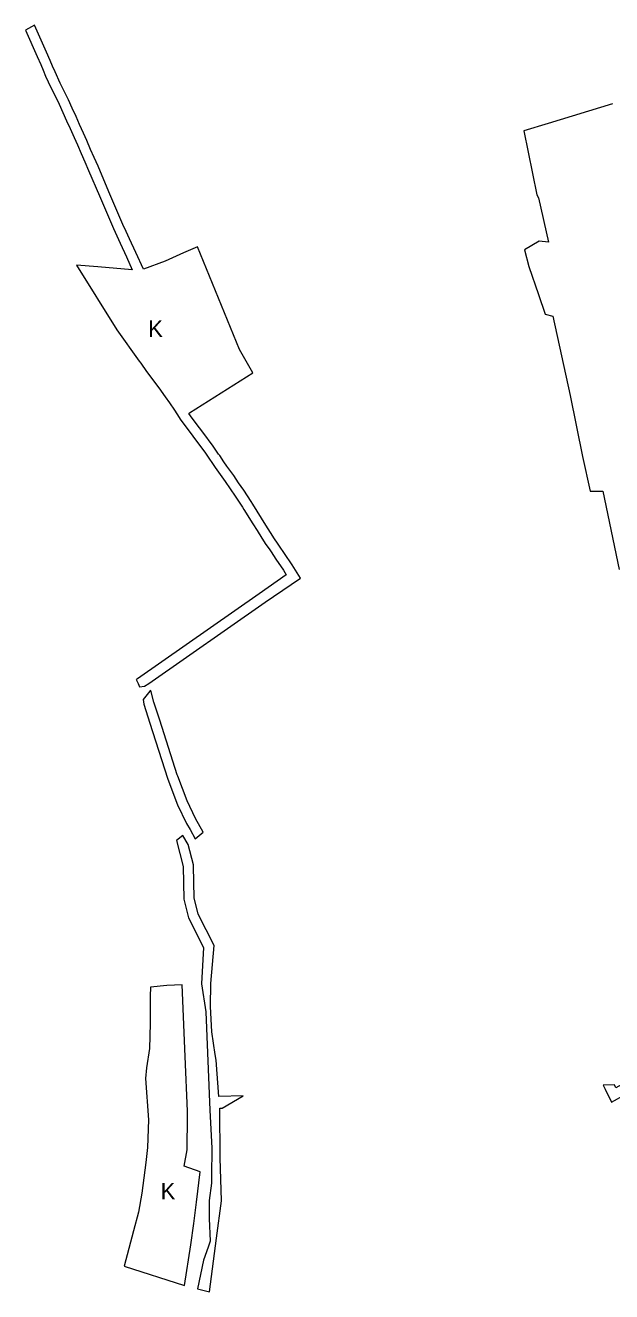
# Model space of a CAD drawing. Extents: x -650276 to -642489, y -1074425 to -1066658.
# Drawn here: x -649558 to -648708, y -1068954 to -1067116 of the extents above; entities that cross this region are included whole.
import ezdxf

# ---------------------------------------------------------------- set-up
doc = ezdxf.new("R2010")
doc.units = 0
doc.header["$LTSCALE"] = 9.6
for name, color, linetype, lineweight in [('1', 7, 'Continuous', 13), ('43', 7, 'Continuous', 13), ('47', 7, 'Continuous', 13)]:
    doc.layers.add(name, color=color, linetype=linetype, lineweight=lineweight)

msp = doc.modelspace()

# ---------------------------------------------------------------- linework, layer by layer
at = {"layer": '1'}
msp.add_lwpolyline([(-648706.47, -1067229.51), (-648800.02, -1067258.42), (-648835.29, -1067268.93), (-648816.06, -1067361.71), (-648813.81, -1067365.91), (-648799.58, -1067430.4), (-648812.91, -1067429.16), (-648834.01, -1067441.81), (-648827.86, -1067465.86), (-648813.94, -1067506.27), (-648804.08, -1067534.88), (-648792.97, -1067537.86), (-648767.84, -1067652.98), (-648749.97, -1067741.49), (-648738.7, -1067792.04), (-648720.34, -1067792), (-648696.93, -1067905.76)], dxfattribs=at)
at = {"layer": '47'}
for points in [[(-649545.203, -1067115.647), (-649549.7, -1067118.05), (-649558.469, -1067122.73), (-649541.537, -1067160.722), (-649536.075, -1067172.622), (-649532.831, -1067180.855), (-649529.013, -1067189.389), (-649521.663, -1067206.124), (-649514.869, -1067218.957), (-649509.44, -1067230.141), (-649504.224, -1067242.225), (-649498.572, -1067254.427), (-649493.526, -1067265.611), (-649487.812, -1067278.312), (-649482.963, -1067288.934), (-649477.677, -1067301.655), (-649472.327, -1067313.644), (-649466.703, -1067326.24), (-649451.059, -1067363.074), (-649439.265, -1067390.397), (-649430.531, -1067410.689), (-649425.804, -1067421.21), (-649421.071, -1067431.944), (-649411.913, -1067451.746), (-649403.34, -1067470.579)], [(-649387.17, -1067469.894), (-649398.28, -1067445.49), (-649407.4, -1067425.77), (-649412.1, -1067415.11), (-649416.8, -1067404.65), (-649425.49, -1067384.46), (-649437.27, -1067357.17), (-649452.95, -1067320.25), (-649458.63, -1067307.53), (-649463.9, -1067295.72), (-649469.21, -1067282.94), (-649474.15, -1067272.12), (-649479.85, -1067259.45), (-649484.93, -1067248.19), (-649490.53, -1067236.1), (-649495.8, -1067223.89), (-649501.49, -1067212.17), (-649508.15, -1067199.59), (-649515.3, -1067183.31), (-649519, -1067175.04), (-649522.27, -1067166.74), (-649527.87, -1067154.54), (-649545.203, -1067115.647)], [(-649321.3, -1067679), (-649320.47, -1067678.44), (-649228.52, -1067620.294), (-649247.518, -1067586.255), (-649308.75, -1067437.11), (-649329.068, -1067446.175), (-649355.44, -1067457.94), (-649387.17, -1067469.894)], [(-649403.34, -1067470.579), (-649453.39, -1067466.13), (-649484.28, -1067463.88), (-649425.69, -1067557.7), (-649393.23, -1067603.28), (-649391.04, -1067606.27), (-649382.53, -1067618.33), (-649364.69, -1067641.98), (-649355.46, -1067654.85), (-649349.12, -1067663.84), (-649341.81, -1067674.33), (-649335.26, -1067685.21), (-649333.74, -1067687.4)], [(-649333.74, -1067687.4), (-649328.34, -1067694.79), (-649317.99, -1067708.85), (-649312.91, -1067715.45), (-649298.02, -1067735.58), (-649290.15, -1067746.92), (-649288.63, -1067748.97), (-649282.85, -1067757.79), (-649278.14, -1067764.31), (-649268.46, -1067777.97), (-649261.48, -1067788.47), (-649253.98, -1067799.2), (-649243.37, -1067815.17), (-649241.28, -1067818.7), (-649228.27, -1067839.26), (-649222.11, -1067849.12), (-649215.32, -1067859.99), (-649209.39, -1067869.34), (-649204.87, -1067875.85), (-649202.02, -1067880.07), (-649194.77, -1067890.67), (-649184, -1067906.88), (-649179.96, -1067913.35), (-649219.088, -1067940.964), (-649395.729, -1068064.23), (-649397.466, -1068065.442), (-649394.83, -1068071.05), (-649392.88, -1068075.9), (-649385.41, -1068075.32), (-649379.295, -1068071.053), (-649210.54, -1067953.29), (-649172.99, -1067927.41), (-649159.179, -1067918.309), (-649171.389, -1067898.756), (-649182.332, -1067882.285), (-649189.614, -1067871.638), (-649192.493, -1067867.375), (-649196.89, -1067861.042), (-649202.625, -1067852), (-649209.388, -1067841.173), (-649215.571, -1067831.276), (-649228.486, -1067810.867), (-649230.661, -1067807.193), (-649241.584, -1067790.752), (-649249.085, -1067780.02), (-649256.092, -1067769.48), (-649265.941, -1067755.582), (-649270.491, -1067749.283), (-649276.322, -1067740.385), (-649277.961, -1067738.175), (-649285.826, -1067726.842), (-649300.936, -1067706.414), (-649306.005, -1067699.828), (-649316.244, -1067685.919), (-649321.3, -1067679)], [(-649376.467, -1068081.552), (-649377.77, -1068082.44), (-649387.46, -1068094.51), (-649386.74, -1068101.31), (-649377.81, -1068129), (-649352.11, -1068208.65)], [(-649352.11, -1068208.65), (-649339.94, -1068241.13), (-649337.52, -1068247.59), (-649324.66, -1068274.3), (-649319.551, -1068283.382), (-649312.087, -1068296.653), (-649300.305, -1068287.002), (-649311.352, -1068267.362), (-649323.711, -1068241.693), (-649337.178, -1068205.751), (-649337.942, -1068203.713), (-649363.534, -1068124.395), (-649371.987, -1068098.185), (-649376.467, -1068081.552)], [(-649330.038, -1068291.976), (-649339.046, -1068299.359), (-649329.644, -1068336.779), (-649328.386, -1068384.468), (-649321.727, -1068411.472), (-649299.894, -1068454.728), (-649302.681, -1068507.363)], [(-649289.24, -1068506.8), (-649284.59, -1068451.76), (-649307.57, -1068406.23), (-649313.42, -1068382.51), (-649314.27, -1068336.41), (-649314.693, -1068334.727), (-649322.18, -1068304.93), (-649330.038, -1068291.976)], [(-649327.679, -1068945.222), (-649318.13, -1068886.42), (-649314.07, -1068855.33), (-649310.01, -1068824.2), (-649304.66, -1068780.33), (-649327.8, -1068771.82), (-649323.68, -1068748.06), (-649323.1, -1068699.28), (-649323.02, -1068692.1), (-649326.53, -1068612.89), (-649331.151, -1068508.557), (-649353.17, -1068509.48), (-649376.77, -1068511.96), (-649377.52, -1068525.1), (-649377.56, -1068564.89), (-649378.08, -1068601.24), (-649382.46, -1068629.34), (-649384.31, -1068644.92), (-649379.97, -1068704.98), (-649381.06, -1068744.69), (-649383.78, -1068766.6)], [(-649302.681, -1068507.363), (-649296.55, -1068548.09), (-649290.93, -1068690.93), (-649287.98, -1068745.74), (-649288.19, -1068786.39), (-649288.24, -1068796.6), (-649291.64, -1068821.88), (-649291.87, -1068848.02), (-649290.28, -1068880.82), (-649293.33, -1068889.65), (-649299.91, -1068908.66), (-649308.65, -1068950), (-649293.04, -1068953.81), (-649291.32, -1068954.23), (-649281.01, -1068876.69), (-649273.66, -1068822.58), (-649275.96, -1068759.73), (-649276.43, -1068688.29), (-649276.474, -1068687.673), (-649272.755, -1068687.618)], [(-649277.655, -1068670.983), (-649281.4, -1068618.05), (-649282.97, -1068610.04), (-649287.71, -1068577.14), (-649289.74, -1068540.2), (-649289.24, -1068506.8)], [(-648551.041, -1068573.16), (-648580.062, -1068590.087), (-648588.022, -1068594.571), (-648653.034, -1068631.191), (-648701.568, -1068658.36), (-648703.816, -1068653.711), (-648720.238, -1068654.205)], [(-648720.238, -1068654.205), (-648717.32, -1068660.24), (-648708.14, -1068679.23), (-648645.69, -1068644.27), (-648643.654, -1068643.123), (-648580.66, -1068607.64), (-648547.25, -1068588.14)], [(-649272.755, -1068687.618), (-649272.69, -1068687.58), (-649242.507, -1068669.925), (-649277.655, -1068670.983)], [(-649383.78, -1068766.6), (-649389.34, -1068811.43), (-649394.48, -1068838.89), (-649401.31, -1068865.78), (-649415.09, -1068917.1), (-649327.679, -1068945.222)]]:
    msp.add_lwpolyline(points, dxfattribs=at)

# ---------------------------------------------------------------- texts
at = {"layer": '43'}
for p in [(-649380.314, -1067568.167), (-649380.314, -1067568.167), (-649362.16, -1068820.233), (-649362.16, -1068820.233)]:
    msp.add_text('K', height=24, dxfattribs=at).set_placement(p)

doc.saveas('drawing.dxf')
